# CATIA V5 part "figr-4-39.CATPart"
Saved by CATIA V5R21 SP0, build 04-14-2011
Part number: Part1
Bounding box of the stored display mesh (mm): x -89.975 to 89.975, y -89.975 to 89.975, z 0 to 190
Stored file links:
  D:\CATIA V5R21 E-RESOURCES\CATIA-V5R21\catia-v5r21-prt\c04-catia-v5r20-prt\catia-v5r21-figr-4-39.CATPart
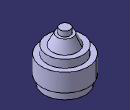
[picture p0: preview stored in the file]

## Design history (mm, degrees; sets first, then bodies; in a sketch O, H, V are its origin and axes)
Set1
  Line1 "Y Axis": stored without definition
  Line2 "Y Axis": stored without definition
  Line3 "X Axis": stored without definition
  Line4 "Z Axis": stored without definition
Body1 (main body)
  Sketch1 on yz-plane, origin (0, 0, 0), H (0, 1, 0), V (0, 0, 1)
    line L1 (0, 0) -> (80, 0)
    line L2 (80, 0) -> (80, 30)
    line L3 (80, 30) -> (90, 30)
    line L4 (90, 30) -> (90, 100)
    line L5 (90, 100) -> (70, 100)
    line L6 (70, 100) -> (70, 130)
    line L7 (70, 130) -> (50, 130)
    line L8 (50, 130) -> (30, 170)
    line L9 (30, 170) -> (20, 170)
    line L10 (20, 170) -> (20, 190)
    line L11 (20, 190) -> (0, 190)
    point P11 (0, 190)
    line L12 (0, 190) -> (0, 0)
    axis line L13 (0, -40) -> (0, 230)
    point P12 (0, -40)
    point P13 (0, 230)
    horizontal: L1 H, L3 H, L5 H, L7 H, L9 H, L11 H
    vertical: L2 V, L4 V, L6 V, L10 V, L12 V, L13 V
    coincidence: P11 V, P12 V, P13 L8
  Shaft1: profile Sketch1, axis Sketch1.L13, angle 360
